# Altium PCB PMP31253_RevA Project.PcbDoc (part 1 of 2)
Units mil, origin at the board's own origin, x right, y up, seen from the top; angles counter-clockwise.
Board outline 7112.5 x 1987.5 mil, 2 copper layers (Top Layer, Bottom Layer), stack 62 mil thick; 96 components, 51 nets, 198 pads, 16 vias.
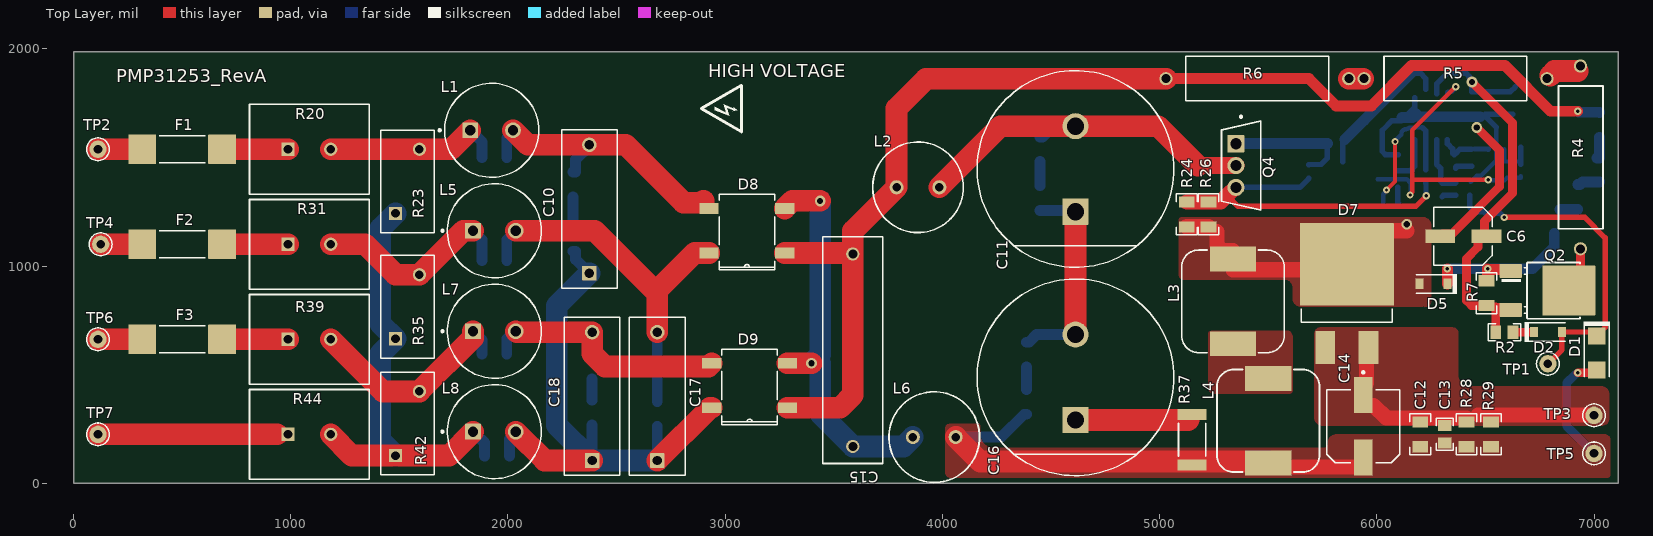
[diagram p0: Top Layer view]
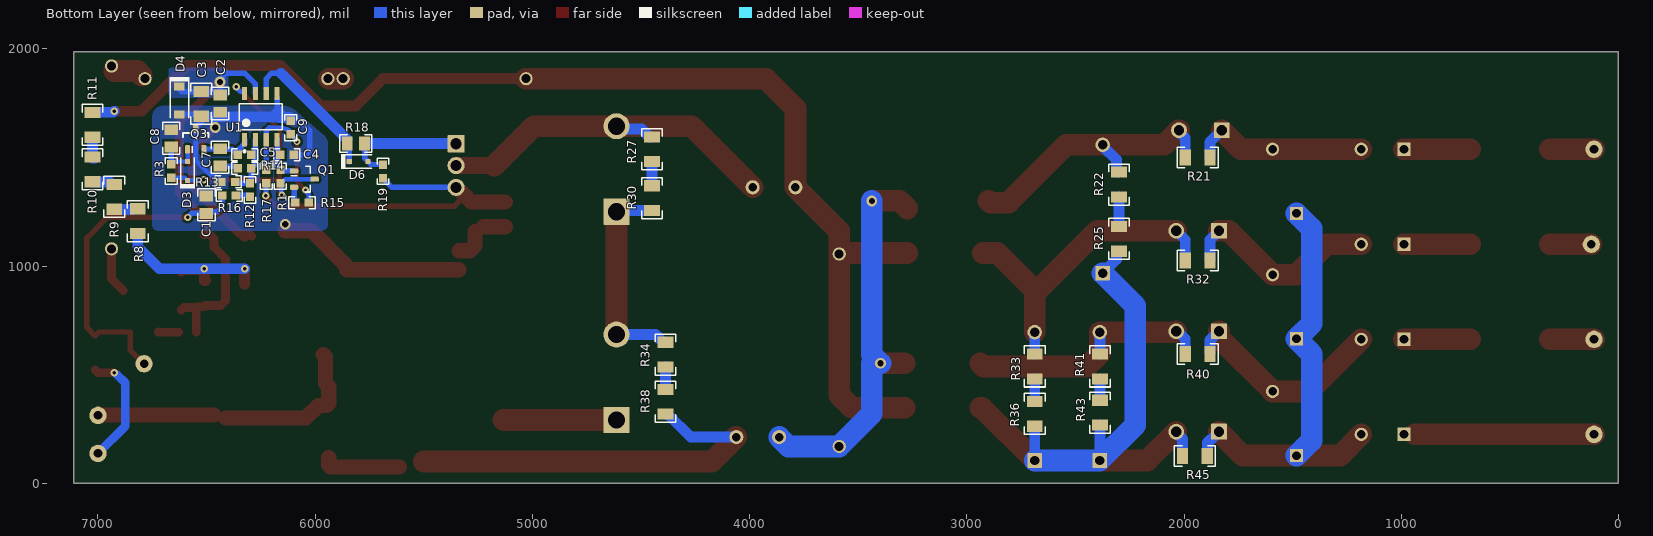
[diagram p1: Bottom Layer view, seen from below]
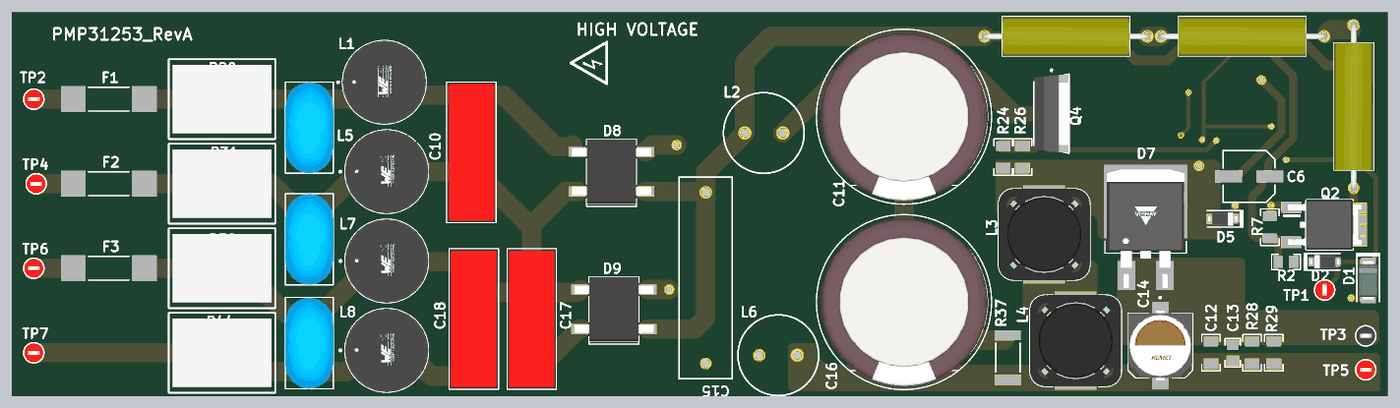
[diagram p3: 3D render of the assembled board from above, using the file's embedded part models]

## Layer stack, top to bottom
Top Solder: solder mask 0.4, Solder Resist, Dk 3.5
Top Layer: signal copper 1.4
Dielectric1: core 59.2, FR-4 High Tg, Dk 4.8
Bottom Layer: signal copper 1.4
Bottom Solder: solder mask 0.4, Solder Resist, Dk 3.5

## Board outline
0,0 7112.5,0 7112.5,1987.5 0,1987.5

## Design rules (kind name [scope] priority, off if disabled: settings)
AcuteAngle [All] p1: minimum=4.50000000000000E+0001 checktracksonly=FALSE
AssemblyTestPointUsage [All] p1: valid=2
BoardOutlineClearance BoardOutlineClearance_MountingHoles [OnCopper and InComponentClass('Mounting Holes')] p1: gap=39.37 ignorepadtopadclearanceinfootprint=FALSE
BoardOutlineClearance BoardOutlineClearance_Poly [OnCopper and IsPoly] p2: gap=25 ignorepadtopadclearanceinfootprint=FALSE
BoardOutlineClearance [OnCopper and Not InComponentClass('Logo') and not InComponentClass('FiducialMark') and not InRegion(1000,500,4000,800) and not InPoly] p3: gap=30 ignorepadtopadclearanceinfootprint=FALSE
Clearance Clearance_Keepouts [((IsTrack Or IsArc) And Not InPoly) And IsFree and IsKeepOut vs ((IsTrack Or IsArc) And Not InPoly) And IsFree and IsKeepOut] p1: gap=0 ignorepadtopadclearanceinfootprint=FALSE
Clearance Clearance_Poly [InPolygon] p2: gap=10 ignorepadtopadclearanceinfootprint=TRUE
Clearance Clearance_FiducialMark [IsKeepOut and InComponentClass('FiducialMark') vs IsPad and InComponentClass('FiducialMark')] p3: gap=0 ignorepadtopadclearanceinfootprint=FALSE
Clearance [All] p4: gap=10 ignorepadtopadclearanceinfootprint=TRUE
ComponentClearance ComponentClearance_MountingHoles_FiducialMarks [InComponentClass('Mounting Holes') vs InComponentClass('FiducialMark')] p1: gap=50 collisioncheckmode=3 verticalgap=10 showdistances=FALSE
ComponentClearance ComponentClearance_Shunt [InComponentClass('Header') vs InComponentClass('Shunt')] p2: gap=0 collisioncheckmode=3 verticalgap=0 showdistances=FALSE
ComponentClearance ComponentClearance_Logo [InComponentClass('Logo')] p3: gap=30 collisioncheckmode=3 verticalgap=10 showdistances=FALSE
ComponentClearance ComponentClearance_ScrewToNut [(HasFootprint('NY PMS 440 0025 PH')) vs (HasFootprint('Keystone_1902C'))] p4: gap=5 collisioncheckmode=3 verticalgap=10 showdistances=FALSE
ComponentClearance ComponentClearance_MountingHoles [InComponentClass('Mounting Holes')] p5: gap=100 collisioncheckmode=3 verticalgap=100000 showdistances=FALSE
ComponentClearance ComponentClearance_SmallPassives [HasFootprint('0201*') or HasFootprint('0402*') or HasFootprint('0508') or HasFootprint('0603*') or HasFootprint('0612') or HasFootprint('0805*') or HasFootprint('0815*') or HasFootprint('0830*') or HasFootprint('1206*') or HasFootprint('1210*') or HasFootprint('1808*') or HasFootprint('1812*') or HasFootprint('1825*') or HasFootprint('2010*') or HasFootprint('2220*') or HasFootprint('2225*') or HasFootprint('2512*') or HasFootprint('2728*') or HasFootprint('3518*') vs HasFootprint('0201*') or HasFootprint('0402*') or HasFootprint('0508') or HasFootprint('0603*') or HasFootprint('0612') or HasFootprint('0805*') or HasFootprint('0815*') or HasFootprint('0830*') or HasFootprint('1206*') or HasFootprint('1210*') or HasFootprint('1808*') or HasFootprint('1812*') or HasFootprint('1825*') or HasFootprint('2010*') or HasFootprint('2220*') or HasFootprint('2225*') or HasFootprint('2512*') or HasFootprint('2728*') or HasFootprint('3518*')] p6: gap=14.96 collisioncheckmode=3 verticalgap=10 showdistances=FALSE
ComponentClearance ComponentClearance_THtoSMT [IsThruComponent vs IsSMTComponent] p7: gap=30 collisioncheckmode=3 verticalgap=30 showdistances=FALSE
ComponentClearance ComponentClearance_THtoTH [IsThruComponent vs IsThruComponent] p8: gap=20 collisioncheckmode=3 verticalgap=30 showdistances=FALSE
ComponentClearance [All] p9: gap=20 collisioncheckmode=3 verticalgap=10 showdistances=FALSE
DiffPairsRouting [All] p1: maxlimit=100 minlimit=10 mostfreqgap=10 toplayer_minwidth=15 toplayer_maxwidth=15 toplayer_prefwidth=15 bottomlayer_minwidth=15 bottomlayer_maxwidth=15 bottomlayer_prefwidth=15 maxuncoupledlength=1000
FabricationTestPointUsage TestPointUsage [All] p1: valid=2 allowmultiple=FALSE
FabricationTestpoint Testpoint [All] p1: side=3 testpointundercomponent=TRUE minsize=40 maxsize=100 preferedsize=60 minholesize=0 maxholesize=40 preferedholesize=32 testpointgrid=1 allowsidetop=TRUE allowsidebottom=TRUE usegrid=TRUE gridtolerance=0.01
FanoutControl Fanout_LCC [IsLCC] p1: bgadir=Out bgaviamode=Centered fanoutstyle=Auto fanoutdirection=Alternating viagrid=1 // Fanout_LCC (Default Rule)
FanoutControl Fanout_BGA [IsBGA] p2: bgadir=Out bgaviamode=Centered fanoutstyle=Auto fanoutdirection=Alternating viagrid=1 // Fanout_BGA (Default Rule)
FanoutControl Fanout_Default [All] p4: bgadir=Out bgaviamode=Centered fanoutstyle=Auto fanoutdirection=Alternating viagrid=1 // Fanout_Default (Default Rule)
FanoutControl Fanout_Small [(CompPinCount < 5)] p5: bgadir=Out bgaviamode=Centered fanoutstyle=Auto fanoutdirection=OutThenIn viagrid=1 // Fanout_Small (Default Rule)
HoleSize [All] p1: absolutevalues=TRUE maxlimit=251 minlimit=7.87 maxpercent=80.000 minpercent=20.000
MinimumAnnularRing MinimumAnnularRing_ThermalPadVias [IsVia and InAnyComponent] p1: minimumring=5.91
MinimumAnnularRing [All] p2: minimumring=7.87
MinimumSolderMaskSliver MinimumSolderMaskSliver_Logo [InComponentClass('Logo') vs InComponentClass('Logo')] p1: minsoldermaskwidth=0.7
MinimumSolderMaskSliver [All] p2: minsoldermaskwidth=3.94
PlaneConnect [All] p1: planeconnectstyle=Relief reliefexpansion=10 reliefentries=4 reliefconductorwidth=10 reliefairgap=10
PolygonConnect [All] p1: connectstyle=Direct reliefconductorwidth=10 reliefentries=4 polygonreliefangle="90 Angle" airgapwidth=10
RoutingVias ThermalPadVias [IsVia and InAnyComponent] p1: holewidth=7.87 width=19.68 viastyle="Through Hole" minholewidth=7.87 minwidth=19.68 maxholewidth=12.99 maxwidth=23.62
RoutingVias [All] p2: holewidth=16 width=34 viastyle="Through Hole" minholewidth=7.87 minwidth=24 maxholewidth=40 maxwidth=65
SilkToBoardRegionClearance [Not ((IsComment or IsDesignator) And (Hide <> 'False')) and not InRegion(1000,500,4000,800)] p1:
SilkToSilkClearance SilkToSilkClearance_Pb-FreeLogo [(HasFootprint('Pb-Free_Overlay_Medium') OR HasFootprint('Pb-Free_Overlay_Small')) vs (HasFootprint('Pb-Free_Overlay_Medium') OR HasFootprint('Pb-Free_Overlay_Small'))] p1 off: silktosilkclearance=0
SilkToSilkClearance [All] p2 off: silktosilkclearance=1
SilkToSolderMaskClearance SilkToComponentPadClearance [(IsPad or IsFill or IsRegion) and InAnycomponent] p1 off: minsilkscreentomaskgap=5 clearancetoexposedcopper=TRUE
SilkToSolderMaskClearance "Silk to Solder Mask Opening" [All] p2 off: minsilkscreentomaskgap=3.94 clearancetoexposedcopper=FALSE
SolderMaskExpansion [All] p1: expansion=1.97 istentingtop=FALSE
UnRoutedNet [All] p1: checkbadconnections=TRUE
Width [All] p1: maxlimit=100 minlimit=6 preferedwidth=10
14 further rules are at their usual default settings.

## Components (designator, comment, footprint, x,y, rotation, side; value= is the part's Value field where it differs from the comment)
C1 "GRM21BR71H224KA01L" 0805_HV 6500.89,1282.12 r90 bottom value=0.22uF
C2 "C0805C104J5RACTU" 0805_HV 6437.5,1748.1 r270 bottom value=0.1uF
C3 "GRM31MR71H105KA88L" 1206 6524.61,1746.34 r270 bottom value=1uF
C4 "GRM188R71H222KA01D" 0603 6130.02,1512.5 r180 bottom value=2200pF
C5 "C0603C682J5RACTU" 0603 6325,1512.5 r0 bottom value=6800pF
C6 "EMVY250ADA330MF55G" CAPSMT_62_F55 6398.29,1137.5 r180 top value=33uF
C7 "C0805C684K5RACTU" 0805_HV 6437.5,1500 r90 bottom value=0.68uF
C8 "GRM21BR71E105KA99L" 0805_HV 6662.5,1587.5 r90 bottom value=DNP
C9 "GRM188R71H221KA01D" 0603 6112.5,1637.5 r90 bottom value=220pF
C10 "890334025027RP" FP-890334025027RP_RADIAL-MFG 2375,1262.5 r90 top value=220nF
C11 "EKMQ401VSN221MP45S" FP-EKMQ401VSN221MP45S_RADIAL-MFG 4612.5,1446.85 r90 top value=220µF
C12 "GCM31MR71E105KA37L" 1206 6200,225 r270 top value=DNP
C13 "GRM21BR71E105KA99L" 0805_HV 6312.5,225 r270 top value=1uF
C14 "A768KE227M1DLAE029" FP-A768KE227M1DLAE029_SMT_CAP_8MM3_8MM3-MFG 5937.5,262.5 r270 top value=220µF
C15 "B32913C5104K000" B32913_2650x700x1600 3587.5,612.5 r270 top value=0.1uF
C16 "EKMQ401VSN221MP45S" FP-EKMQ401VSN221MP45S_RADIAL-MFG 4612.5,487.5 r90 top value=220µF
C17 "890334025027RP" FP-890334025027RP_RADIAL-MFG 2687.5,400 r90 top value=220nF
C18 "890334025027RP" FP-890334025027RP_RADIAL-MFG 2387.5,400 r90 top value=220nF
D1 "RS1K-13-F" SMA 7012.5,600 r270 top value=800V
D2 "1N4148W-7-F" SOD-123 6787.5,696.23 r0 top value=100V
D3 "DNP" SOD-323 6587.5,1437.5 r90 bottom
D4 "MMSZ4705-HE3-08" SOD-123 6625,1762.5 r270 bottom value=DNP
D5 "MMSZ5234B-7-F" SOD-123 6260.53,917.68 r180 top value=6.2V
D6 "MMDL914-TP" SOD-323 5800,1480.81 r180 bottom value=100V
D7 "VS-10ETS08STRL-M3" FP-VS-10ETS08STRL-M3_D2PAK-MFG 5861.91,930.22 r0 top
D8 "DF08S-E3" DF-S 3100,1162.5 r180 top value=800V
D9 "DF08S-E3" DF-S 3112.5,450 r180 top value=800V
F1 "04611.25ER" FP-04611.25ER_SMT_FUSE_10MM10_3MM12-MFG 500,1537.5 r0 top
F2 "04611.25ER" FP-04611.25ER_SMT_FUSE_10MM10_3MM12-MFG 500,1100 r0 top
F3 "04611.25ER" FP-04611.25ER_SMT_FUSE_10MM10_3MM12-MFG 500,662.5 r0 top
"HIGH VOLTAGE" "DANGER HIGH VOLTAGE" IEC_HighVoltage_Small 2987.5,1725 r90 top (schematic designator "HIGH VOLTAGE?")
L1 "7447471222" FP-7447471222_RADIAL-MFG 1925,1625 r0 top value=SHORT
L2 "7447480101" WE-TI_1014 3887.5,1362.5 r0 top value=100uH
L3 "7687709221" WE_PD-HV_1210 5337.5,837.5 r90 top value=220uH
L4 "7687709221" WE_PD-HV_1210 5500,287.5 r90 top value=220uH
L5 "7447471222" FP-7447471222_RADIAL-MFG 1937.5,1162.5 r0 top value=SHORT
L6 "7447480101" WE-TI_1014 3962.5,212.5 r0 top value=100uH
L7 "7447471222" FP-7447471222_RADIAL-MFG 1937.5,700 r0 top value=SHORT
L8 "7447471222" FP-7447471222_RADIAL-MFG 1937.5,237.5 r0 top value=SHORT
Q1 "MMBT3904-7-F" SOT-23 6050,1400 r180 bottom value=DNP
Q2 "IXTY1R6N100D2" DPAK 6750,887.5 r0 top value=1000V
Q3 "MMBT2907A" SOT-23 6549.9,1584.74 r90 bottom value=DNP
Q4 "STP80N240K6" FP-STP7N105K5_TO-220AB-MFG 5375,1462.5 r0 top
R1 "CRCW060335K7FKEA" 0603 6160.36,1412.5 r270 bottom value=35.7k
R2 "CRCW08050000Z0EAHP" 0805_HV 6587.5,695.24 r0 top value=0
R3 "CRCW06031M50JNEA" 0603 6662.5,1437.5 r270 bottom value=DNP
R4 "PR03000201502JAC00" PR03 6937.5,1500 r90 top value=15k
R5 "PR03000201502JAC00" PR03 6362.5,1862.5 r180 top value=15k
R6 "PR03000201502JAC00" PR03 5450,1862.5 r180 top value=15k
R7 "CRCW1206301KFKEA" 1206 6504.59,875 r90 top value=301k
R8 "CRCW1206200KJNEA" 1206 6816.73,1206.49 r90 bottom value=200k
R9 "CRCW1206200KJNEA" 1206 6925,1318.5 r90 bottom value=200k
R10 "CRCW1206200KJNEA" 1206 7025,1444.98 r90 bottom value=200k
R11 "CRCW1206200KJNEA" 1206 7025,1650 r90 bottom value=200k
R12 "CRCW060310K0FKEA" 0603 6300,1350 r90 bottom value=10.0k
R13 "CRCW06032K61FKEA" 0603 6400,1387.5 r180 bottom value=2.61k
R14 "RC0603FR-072KL" 0603 6325,1450 r180 bottom value=2.00k
R15 "CRCW06031M50JNEA" 0603 6060.69,1291.88 r0 bottom value=DNP
R16 "CRCW06030000Z0EA" 0603 6396,1324.87 r180 bottom value=0
R17 "CRCW06033K83FKEA" 0603 6225,1412.5 r90 bottom value=3.83k
R18 "CRCW080510R0JNEA" 0805_HV 5812.5,1563.88 r0 bottom value=10
R19 "CRCW0603100KFKEA" 0603 5687.5,1435.69 r270 bottom value=100k
R20 "SQMW522RJ" FP-SQMW547RJ_RADIAL-MFG 1085.93,1537.5 r0 top
R21 "CRCW120610K0FKEAHP" 1206 1937.5,1500 r0 bottom value=DNP
R22 "CRCW1206100KJNEA" 1206 2300,1375 r90 bottom value=TBD
R23 "DNP" FP-B72210S0461K101_RADIAL-MFG 1537.5,1389.86 r90 top
R24 "ERJ-8RQFR56V" 1206 5225,1237.5 r90 top value=0.56
R25 "CRCW1206100KJNEA" 1206 2300,1125 r90 bottom value=TBD
R26 "DNP" 1206 5125,1237.5 r270 top
R27 "CRCW1206" 1206 4450,1537.5 r90 bottom value=750k
R28 "CRCW12065K10JNEA" 1206 6412.5,225 r90 top value=5.1k
R29 "CRCW12065K10JNEA" 1206 6525,225 r90 top value=5.1k
R30 "CRCW1206" 1206 4450,1312.5 r90 bottom value=750k
R31 "SQMW522RJ" FP-SQMW547RJ_RADIAL-MFG 1085.93,1100 r0 top
R32 "CRCW120610K0FKEAHP" 1206 1937.5,1025 r0 bottom value=DNP
R33 "CRCW1206100KJNEA" 1206 2687.5,537.5 r90 bottom value=TBD
R34 "CRCW1206" 1206 4387.5,592.22 r90 bottom value=750k
R35 "DNP" FP-B72210S0461K101_RADIAL-MFG 1537.5,812.5 r90 top
R36 "CRCW1206100KJNEA" 1206 2687.5,319.59 r90 bottom value=TBD
R37 "CRM2512-FX-15R0" 2512 5150,200 r90 top value=SHORT
R38 "CRCW1206" 1206 4387.5,375 r90 bottom value=750k
R39 "SQMW522RJ" FP-SQMW547RJ_RADIAL-MFG 1085.93,662.5 r0 top
R40 "CRCW120610K0FKEAHP" 1206 1937.5,594.59 r0 bottom value=DNP
R41 "CRCW1206100KJNEA" 1206 2387.5,537.5 r90 bottom value=TBD
R42 "DNP" FP-B72210S0461K101_RADIAL-MFG 1537.5,275 r90 top
R43 "CRCW1206100KJNEA" 1206 2387.5,325 r90 bottom value=TBD
R44 "SQMW522RJ" FP-SQMW547RJ_RADIAL-MFG 1085.93,225 r0 top
R45 "CRCW120610K0FKEAHP" 1206 1950,125 r0 bottom value=DNP
TP1 "5000" Keystone5000 6787.5,550 r0 top
TP2 "5000" Keystone5000 112.5,1537.5 r90 top
TP3 "5001" Keystone5001 7000,312.5 r90 top
TP4 "5000" Keystone5000 125,1100 r90 top
TP5 "5000" Keystone5000 7000,137.5 r90 top
TP6 "5000" Keystone5000 112.5,662.5 r90 top
TP7 "5000" Keystone5000 112.5,225 r90 top
U1 "UCC28C55DR" D0008A-MFG 6250,1687.5 r90 bottom

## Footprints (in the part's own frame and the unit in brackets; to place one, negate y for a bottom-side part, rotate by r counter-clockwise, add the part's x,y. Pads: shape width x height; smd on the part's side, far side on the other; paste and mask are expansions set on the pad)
0603 [mm] "0603 from SM-752 data"
  rect 1x0.95 smd: 1(-0.8,0) 2(0.8,0)
  silkscreen extent -1.52,-0.69 1.52,0.69, body extent -0.87,-0.47 0.87,0.47, height 1
0805_HV [mil] "0805 with 30mil clearance between pads"
  rect 50x63 smd: 1(-40,0) 2(40,0)
  silkscreen extent -74,-40 74,40, body extent -43,-29 43,29, height 57
1206 [mm] "1206 from SM-752 data"
  rect 1.3x1.85 smd: 1(-1.45,0) 2(1.45,0)
  silkscreen extent -2.4,-1.21 2.4,1.21, body extent -1.7,-0.9 1.7,0.9, height 1.35
2512 [mm] "Chip Resistor, Body 6.3x3.2mm, IPC Medium Density"
  rect 1.3x3.4 smd: 1(-2.95,0) 2(2.95,0)
  silkscreen extent -1.9,-1.6 1.9,1.6, body extent -3.22,-1.67 3.22,1.67, height 0.71
B32913_2650x700x1600 [mm] "TH, 2-Leads, Body 26.5x7mm, Pin Spacing 22.5mm"
  round 1.55 hole 1.05: 1(-11.25,0) 2(11.25,0)
  silkscreen extent -13.25,-3.5 13.25,3.5, body extent -13.25,-3.5 13.25,3.5, height 16
CAPSMT_62_F55 [mm] "6.3 x 5.2mm:  Chemi-Con F55"
  rect 3.5x1.6 smd: 1(-2.7,0) 2(2.7,0)
  silkscreen extent -3.36,-3.4 3.44,3.4, body extent -3.4,-3.4 3.44,3.4, height 5.5
D0008A-MFG [mm]
  rrect17% 1.55x0.6 smd paste+0 mask+0: 1(-2.7,1.905) 2(-2.7,0.635) 3(-2.7,-0.635) 4(-2.7,-1.905) 5(2.7,-1.905) 6(2.7,-0.635) 7(2.7,0.635) 8(2.7,1.905)
  silkscreen extent -4.17,-2.5 1.5,2.5, body extent -3,-2.45 3,2.45, height 1.75
DF-S [mil] "Diodes Inc. recommended land pattern per ap02001.pdf rev 30"
  rect 88x49 smd: 1(-174.5,102.36) 2(-174.5,-102.36) 3(174.5,-102.36) 4(174.5,102.36)
  silkscreen extent -128,-168 128,180, body extent -205,-168 205,168, height 108
DPAK [mm] "D-PAK, 3-Pads, Body 6.22x6.73mm (max), TO-252AA using nominal STEP model"
  rrect6% 2.6x1.6 smd: 1(-3.4,2.28) 3(-3.4,-2.28)
  rrect2% 6.2x5.8 smd paste-2.9: 4(3.4,0)
  silkscreen extent -4.5,-3.3 4.7,3.28, body extent -3.86,-3.29 5.84,3.29, height 2.48
FP-04611.25ER_SMT_FUSE_10MM10_3MM12-MFG [mm]
  rrect3% 3.25x3.43 smd paste+0 mask+0: 1(-4.675,0) 2(4.675,0)
  silkscreen extent -2.68,-1.56 2.68,1.56, body extent -6.4,-1.82 6.4,1.82, height 0.25
FP-7447471222_RADIAL-MFG [mm]
  rrect5% 1.85x1.85 hole 1.2 paste-1000 mask+0: 1(-2.5,0)
  round 1.85 hole 1.2 paste-1000 mask+0: 2(2.5,0)
  silkscreen extent -6.2,-5.5 5.5,5.5, body extent -5.6,-5.6 5.6,5.6, height 0.25
FP-890334025027RP_RADIAL-MFG [mm]
  rrect6% 1.7x1.7 hole 1.1 paste-1000 mask+0: 1(-7.5,0)
  round 1.7 hole 1.1 paste-1000 mask+0: 2(7.5,0)
  silkscreen extent -9.25,-3.25 9.25,3.25, body extent -9.35,-3.35 9.35,3.35, height 0.25
FP-A768KE227M1DLAE029_SMT_CAP_8MM3_8MM3-MFG [mm]
  rrect5% 4.2x2.2 smd paste+0 mask+0: 1(-3.65,0) 2(3.65,0)
  silkscreen extent -6.42,-4.25 4.25,4.25, body extent -6,-4.5 6,4.5, height 0.25
FP-B72210S0461K101_RADIAL-MFG [mm]
  rrect6% 1.55x1.55 hole 1 paste-1000 mask+0: 1(-3.75,1.4)
  round 1.55 hole 1 paste-1000 mask+0: 2(3.75,-1.4)
  silkscreen extent -6,-3.15 6,3.15, body extent -6.1,-3.25 6.1,3.25, height 0.25
FP-EKMQ401VSN221MP45S_RADIAL-MFG [mm]
  rrect3% 3.05x3.05 hole 2 paste-1000 mask+0: 1(-5,0)
  round 3.05 hole 2 paste-1000 mask+0: 2(5,0)
  silkscreen extent -11.5,-11.5 11.5,11.5, body extent -11.6,-11.6 11.6,11.6, height 0.25
FP-SQMW547RJ_RADIAL-MFG [mm]
  rrect6% 1.55x1.55 hole 1 paste-1000 mask+0: 1(-2.5,0)
  round 1.55 hole 1 paste-1000 mask+0: 2(2.5,0)
  silkscreen extent -7,-5.25 7,5.25, body extent -7.1,-5.35 7.1,5.35, height 0.25
FP-STP7N105K5_TO-220AB-MFG [mm]
  rrect5% 2x2 hole 1.3 paste-1000 mask+0: 1(-0.605,2.55)
  round 2 hole 1.3 paste-1000 mask+0: 2(-0.605,0) 3(-0.605,-2.55)
  silkscreen extent -2.3,-5.2 2.3,5.82, body extent -2.4,-5.3 2.4,5.3, height 0.25
FP-VS-10ETS08STRL-M3_D2PAK-MFG [mm]
  rrect4% 2.32x3.81 smd paste+0 mask+0: 1(-2.525,-7.752) 3(2.525,-7.752)
  rrect1% 11x9.65 smd paste+0 mask+0: 4(0,1.967)
  silkscreen extent -5.34,-4.82 5.34,-3.23, body extent -5.6,-9.76 5.6,6.89, height 0.25
IEC_HighVoltage_Small [mil]
  silkscreen extent -107,-88 107,97
Keystone5000 [mil] "For Keystone 500x miniature loop terminals"
  round 80 hole 40: 1(0,0)
  silkscreen extent -52,-52 52,52, body extent -49,-49 49,49, height 182
Keystone5001 [mil] "For Keystone 500x miniature loop terminals"
  round 80 hole 40: 1(0,0)
  silkscreen extent -52,-52 52,52, body extent -49,-49 49,49, height 182
PR03 [mm] "TH, 2-Leads, Axial, Dia 5.2mm, Pin Spacing 21.38mm"
  round 1.55 hole 1.05: 1(-10.69,0) 2(10.69,0)
  silkscreen extent -8.34,-2.63 8.36,2.57, body extent -11.08,-2.6 11.08,2.6, height 5.22
SMA [mm] "Molded Diode, 2-Leads, Body 4.3x2.6mm, IPC Medium Density, based on OnSemi component dimensions and land pattern"
  rect 2x2 smd: 1(-2,0) 2(2,0)
  silkscreen extent -3.66,-1.57 2.79,1.57, body extent -2.6,-1.3 2.6,1.3, height 2.42
SOD-123 [mm] "On Semi recommended land pattern"
  rect 0.915x1.22 smd: 1(-1.637,0) 2(1.637,0)
  silkscreen extent -2.74,-1.17 2.03,1.17, body extent -1.93,-0.9 1.93,0.9, height 1.35
SOD-323 [mm] "NXP recommended land pattern"
  rect 0.6x0.6 smd paste-0.05: 1(-1.1,0) 2(1.1,0)
  silkscreen extent -2.06,-0.86 1.53,0.86, body extent -1.3,-0.67 1.3,0.68, height 1.1
SOT-23 [mm] "SOT23, 3-Leads, Body 2.9x1.3mm, Pitch 0.95mm, Lead Span 2.5mm, IPC Medium Density"
  rrect50% 1x0.6 smd: 1(-1.2,0.95) 2(-1.2,-0.95) 3(1.2,0)
  silkscreen extent -1.63,-1.5 0.7,1.5, body extent -1.16,-1.45 1.21,1.45, height 1
WE-TI_1014 [mm] "WURTH"
  round 1.65 hole 1: 1(-2.5,0) 2(2.5,0)
  silkscreen extent -5.3,-5.3 5.3,5.3, body extent -5.25,-5.25 5.25,5.25, height 14.5
WE_PD-HV_1210 [mm] "SMD, 2-Leads, Body 12x12mm"
  rect 2.9x5.4 smd: 1(-4.95,0) 2(4.95,0)
  silkscreen extent -6,-6 6,6, body extent -6,-6 6,6, height 9.7

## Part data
C1: library part CMP-0008354-1, "CAP, CERM, 0.22 uF, 50 V, +/- 10%, X7R, 0805", Cap_Case=0805, Manufacturer=MuRata, Supplier Part Number 1=490-1670-1-ND, TempCo=X7R, Tolerance_%=10%, Value1=Unknown, Value2=50V, ValueDisplayed=0.22uF
C2: library part CMP-0007721-2, "CAP, CERM, 0.1 uF, 50 V, +/- 5%, X7R, 0805", Cap_Case=0805, Manufacturer=Kemet, Supplier Part Number 1=64K2889, TempCo=X7R, Tolerance_%=5%, Value1="0.064 ohm", Value2=50V, ValueDisplayed=0.1uF
C3: library part CMP-0008992-2, "CAP, CERM, 1 uF, 50 V, +/- 10%, X7R, 1206", Cap_Case=1206, Manufacturer=MuRata, Supplier Part Number 1=GRM31MR71H105KA88L-ND, TempCo=X7R, Tolerance_%=10%, Value1=Unknown, Value2=50V, ValueDisplayed=1uF
C4: library part CMP-0007443-4, "CAP, CERM, 2200 pF, 50 V, +/- 10%, X7R, 0603", Cap_Case=0603, Manufacturer=MuRata, Supplier Part Number 1=490-1500-1-ND, TempCo=X7R, Tolerance_%=10%, Value1=Unknown, Value2=50V, ValueDisplayed=2200pF
C5: library part CMP-0006961-4, "CAP, CERM, 6800 pF, 50 V, +/- 5%, X7R, 0603", Cap_Case=0603, Manufacturer=Kemet, Supplier Part Number 1=399-1090-1-ND, TempCo=X7R, Tolerance_%=5%, Value1=Unknown, Value2=50V, ValueDisplayed=6800pF
C6: library part CMP-0010994-1, "CAP, AL, 33 uF, 25 V, +/- 20%, 1 ohm, SMD", Cap_Case=F55, Manufacturer=Chemi-Con, Supplier Part Number 1=565-2460-1-ND, Tolerance_%=20%, Value1="1 ohm", Value2=25V, ValueDisplayed=33uF
C7: library part CMP-0007814-2, "CAP, CERM, 0.68 uF, 50 V, +/- 10%, X7R, 0805", Cap_Case=0805, Manufacturer=Kemet, Supplier Part Number 1=399-8114-6-ND, TempCo=X7R, Tolerance_%=10%, Value1=Unknown, Value2=50V, ValueDisplayed=0.68uF
C8: library part CMP-0008336-1, "DNP", Cap_Case=0805, Manufacturer=MuRata, Supplier Part Number 1=GRM21BR71E105KA99L-ND, TempCo=X7R, Tolerance_%=10%, Value1=Unknown, Value2=25V, ValueDisplayed=1uF
C9: library part CMP-0007442-3, "CAP, CERM, 220 pF, 50 V, +/- 10%, X7R, 0603", Cap_Case=0603, Manufacturer=MuRata, Supplier Part Number 1=490-1483-1-ND, TempCo=X7R, Tolerance_%=10%, Value1=Unknown, Value2=50V, ValueDisplayed=220pF
C10 C17 C18: library part CMP-0096484-1, "0.22 µF Film Capacitor 630V Polypropylene (PP), Metallized Radial", Manufacturer="Wurth Electronics", Operating Temperature Range="-40°C to +105°C", Tolerance_%=10%, ValueDisplayed=220nF, Voltage Ac Rating X=310V
C11 C16: library part CMP-0001412-1, "Cap Aluminum Lytic 220uF 400V 20% (22 X 45mm) Snap-In 10mm 1100mA 2000h 105°C", Digikey Part Number=565-3002-ND, Leakage Current=889uA, Manufacturer="United Chemi-Con", Mouser Part Number=661-EKMQ401N221MP45S, Operating Temperature Range="-25°C to +105°C", Tolerance_%=20%, ValueDisplayed=220uF
C12: library part CMP-0008817-1, "DNP", Cap_Case=1206, Manufacturer=MuRata, Supplier Part Number 1=490-6066-1-ND, TempCo=X7R, Tolerance_%=10%, Value1=Unknown, Value2=25V
C13: library part CMP-0008336-1, "CAP, CERM, 1 uF, 25 V, +/- 10%, X7R, 0805", Cap_Case=0805, Manufacturer=MuRata, Supplier Part Number 1=GRM21BR71E105KA99L-ND, TempCo=X7R, Tolerance_%=10%, Value1=Unknown, Value2=25V, ValueDisplayed=1uF
C14: library part CMP-0001409-1, "220 µF 20 V Aluminum - Polymer Capacitors Radial, Can - SMD 29mOhm 2000 Hrs @ 125°C", Digikey Part Number=399-A768KE227M1DLAE029CT-ND, Leakage Current=880uA, Manufacturer=KEMET, Mouser Part Number=80-A768KE227M1DLAE29, Operating Temperature Range="-55°C to +125°C", Tolerance_%=20%, ValueDisplayed=220uF
C15: library part CMP-0012372-1, "CAP, Film, 0.1 uF, 1000 V, +/- 10%, TH", Cap_Case=26.5x7x16mm, Manufacturer=TDK, Supplier Part Number 1=B32913C5104K-ND, Tolerance_%=10%, Value1=Unknown, Value2=1000V, ValueDisplayed=0.1uF
D1: library part CMP-0029004-2, "Diode, Ultrafast, 800 V, 1 A, SMA", Manufacturer="Diodes Inc.", Value1=1A, Value2=1.3V
D2: library part CMP-0029001-1, "Diode, Ultrafast, 100 V, 0.15 A, SOD-123", Manufacturer="Diodes Inc.", Supplier Part Number 1=1N4148W-FDICT-ND, Value1=0.15A, Value2=1.25V
D3: library part CMP-0082069-2, Manufacturer="Micro Commercial Components", Value1=0.15A, Value2=1V
D4: library part CMP-0077578-1, "DNP", Manufacturer=Vishay-Semiconductor, Power_W=500mW, Supplier Part Number 1=MMSZ4705-HE3-08-ND, Value1=0.5W
D5: library part CMP-0005805-3, "Diode, Zener, 6.2 V, 500 mW, SOD-123", Manufacturer="Diodes Inc.", Power_W=500mW, Value1=0.5W
D6: library part CMP-0029045-1, "Diode, Switching, 100 V, 0.2 A, SOD-323", Manufacturer="Micro Commercial Components", Supplier Part Number 1=MMDL914-TPMSCT-ND, Value1=0.2A, Value2=1V
D7: library part CMP-0001428-1, "Rectifier Diode Switching 800V 10A 3-Pin(2+Tab) D2PAK T/R", Digikey Part Number=112-VS-10ETS08STRL-M3CT-ND, Forward Current=10A, Manufacturer=Vishay, Max Surge Forward Current=160A, Mouser Part Number=78-VS-10ETS08STRL-M3, Operating Temperature Range="-40°C to +150°C", Peak Reverse Current=0.05mA
D8 D9: library part CMP-0029219-1, "Diode, Switching-Bridge, 800 V, 1 A, DF-S", Manufacturer=Vishay-Semiconductor, Supplier Part Number 1=DF08S-E3/45GI-ND, Value1=1A, Value2=1.1V
F1 F2 F3: library part CMP-0001488-1, "Fuse Chip Slow Blow Acting 1.25A 600V SMD Solder Pad 10.1 X 3.12 X 3.12mm Ceramic T/R", Digikey Part Number=F1550CT-ND, Fuse Current=1.25A, Fuse Interrupt Dc Current=100A, Manufacturer="Littelfuse Inc", Mouser Part Number=576-04611.25ER, Operating Temperature Range="-55°C to +125°C"
"HIGH VOLTAGE": library part CMP-0074835-1, "IEC 61010-1 High Voltage Warning"
L1 L5 L7 L8: library part CMP-0096506-1, "2.2 mH Shielded Drum Core, Wirewound Inductor 400 mA 2.7Ohm Max Radial, Vertical Cylinder", Digikey Part Number=732-4211-ND, Manufacturer="Wurth Electronics", Mouser Part Number=710-7447471222, Operating Temperature Range="-40°C to +125°C", PartNumber=SHORT, Self Resonant Frequency=740kHz, Test Frequency=10kHz, Tolerance_%=10%
L2 L6: library part CMP-0064523-2, "Inductor, Wirewound, Ferrite, 100 uH, 2.4 A, 0.1 ohm, TH", Manufacturer="Wurth Elektronik", Supplier Part Number 1=732-4193-ND, Value1="0.1 ohm", Value2=2.4A, ValueDisplayed=TBD
L3 L4: library part CMP-0064845-2, "Inductor, Wirewound, 220 uH, 1.3 A, 0.3 ohm, SMD", Manufacturer="Wurth Elektronik", Supplier Part Number 1=732-4543-2-ND, Value1="0.3 ohm", Value2=1.3A, ValueDisplayed=220uH
Q1: library part CMP-0000387-2, "Transistor, NPN, 40 V, 0.2 A, SOT-23", Manufacturer="Diodes Inc.", PartNumber=DNP, Supplier Part Number 1=MMBT3904-FDICT-ND, Value1="0.2 A", Value2=400
Q2: library part CMP-0067585-1, "MOSFET, N-CH, 1000V, DPAK", Alternate Manufacturer=None, Manufacturer=IXYS, Value1="? ohm"
Q3: library part CMP-0000331-2, "Transistor, PNP, 60 V, 0.8 A, SOT-23", Manufacturer="Fairchild Semiconductor", PartNumber=DNP, Supplier Part Number 1=MMBT2907AFSCT-ND
Q4: library part CMP-0088481-1, "N-Channel 800V Through Hole TO-220", Drain To Source Breakdown Voltage=1050V, Manufacturer=STMicroelectronics, Operating Temperature Range="-55°C to +150°C"
R1: library part CMP-0022352-2, "RES, 35.7 k, 1%, 0.1 W, 0603", Manufacturer=Vishay-Dale, Power_W=100mW, Supplier Part Number 1=541-35.7KHCT-ND, TempCo="100 ppm/C", Tolerance_%=1%, Value2=0.1W, Value_Code=35k7, ValueDisplayed=35.7k
R2: library part CMP-0020443-2, "RES, 0, 5%, 0.333 W, 0805", Manufacturer=Vishay-Dale, Power_W=333mW, Supplier Part Number 1=541-0.0TBCT-ND, TempCo="200 ppm/C", Tolerance_%=5%, Value2=0.333W, Value_Code=0000, ValueDisplayed=0
R3 R15: library part CMP-0025740-1, "DNP", Manufacturer=Vishay-Dale, Power_W=100mW, Supplier Part Number 1=541-1.5MGCT-ND, TempCo="200 ppm/C", Tolerance_%=5%, Value2=0.1W, Value_Code=1M50
R4 R5 R6: library part CMP-0014427-2, "RES, 15 k, 5%, 3 W, D5.20xL16.70mm", Manufacturer=Vishay-Bccomponents, Power_W=3W, Supplier Part Number 1=PPC15KW-3JCT-ND, TempCo="250 ppm/C", Tolerance_%=5%, Value_Code=15k0, ValueDisplayed=15k
R7: library part CMP-0016895-2, "RES, 301 k, 1%, 0.25 W, 1206", Manufacturer=Vishay-Dale, Power_W=250mW, Supplier Part Number 1=541-301KFCT-ND, TempCo="100 ppm/C", Tolerance_%=1%, Value2=0.25W, Value_Code=301k
R8 R9 R10 R11: library part CMP-0018624-3, "RES, 200 k, 5%, 0.25 W, AEC-Q200 Grade 0, 1206", Manufacturer=Vishay-Dale, Power_W=250mW, Supplier Part Number 1=541-200KECT-ND, TempCo="200 ppm/C", Tolerance_%=5%, Value2=0.25W, Value_Code=200k
R12: library part CMP-0021998-1, "RES, 10.0 k, 1%, 0.1 W, 0603", Manufacturer=Vishay-Dale, Power_W=100mW, Supplier Part Number 1=541-10.0KHCT-ND, TempCo="100 ppm/C", Tolerance_%=1%, Value2=0.1W, Value_Code=10k0, ValueDisplayed=10.0k
R13: library part CMP-0022279-4, "RES, 2.61 k, 1%, 0.1 W, AEC-Q200 Grade 0, 0603", Manufacturer=Vishay-Dale, Power_W=100mW, Supplier Part Number 1=541-2.61KHCT-ND, TempCo="100 ppm/C", Tolerance_%=1%, Value2=0.1W, Value_Code=2k61, ValueDisplayed=2.61k
R14: library part CMP-0023000-5, "RES, 2.00 k, 1%, 0.1 W, 0603", Manufacturer=Yageo, Power_W=100mW, Supplier Part Number 1=311-2.00KHRCT-ND, TempCo="100 ppm/C", Tolerance_%=1%, Value2=0.1W, Value_Code=2k00, ValueDisplayed=2.00k
R16: library part CMP-0025697-1, "RES, 0, 5%, 0.1 W, 0603", Manufacturer=Vishay-Dale, Power_W=100mW, Supplier Part Number 1=541-0.0GCT-ND, TempCo="200 ppm/C", Tolerance_%=5%, Value2=0.1W, Value_Code=0000, ValueDisplayed=0
R17: library part CMP-0022381-1, "RES, 3.83 k, 1%, 0.1 W, 0603", Manufacturer=Vishay-Dale, Power_W=100mW, Supplier Part Number 1=541-3.83KHCT-ND, TempCo="100 ppm/C", Tolerance_%=1%, Value2=0.1W, Value_Code=3k83, ValueDisplayed=3.83k
R18: library part CMP-0020448-1, "RES, 10, 5%, 0.125 W, 0805", Manufacturer=Vishay-Dale, Power_W=125mW, Supplier Part Number 1=541-10ACT-ND, TempCo="200 ppm/C", Tolerance_%=5%, Value2=0.125W, Value_Code=10R0, ValueDisplayed=10
R19: library part CMP-0021990-3, "RES, 100 k, 1%, 0.1 W, 0603", Manufacturer=Vishay-Dale, Power_W=100mW, Supplier Part Number 1=541-100KHCT-ND, TempCo="100 ppm/C", Tolerance_%=1%, Value2=0.1W, Value_Code=100k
